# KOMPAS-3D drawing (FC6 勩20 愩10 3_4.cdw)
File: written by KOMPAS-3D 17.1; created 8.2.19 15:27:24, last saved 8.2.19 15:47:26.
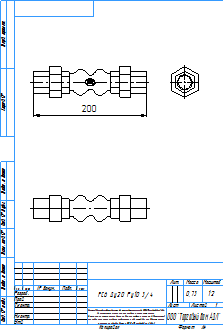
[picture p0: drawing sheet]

Sheet 1: A4, portrait

Title block, sheet 1: name: FC6 Ду20 Ру10 3/4; mass: 0,73; sheets: 1; sheet format: A4; stored path: \\adlc.lan\data\АДЛ_ПКД\3D-модели\ADL production\Гибкие вставки серии FC\FC6\KOMPAS 2D\FC6 Ду20 Ру10 3_4.cdw

Views: Вид 1
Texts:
  kka
  adl
  Рама для чертежей
  Лит-Масса-Масштаб
  Материал-Предприятие
  Масштаб
  Изм.
  Лист
  № докум.
  Подп.
  Дата
  Лит.
  Разраб.
  Пров.
  Т.контр.
  Листов
  Внимание! Данный продукт является объектом авторского права ООО «Торговый Дом АДЛ».
  Запрещается изменение, копирование, распространение
  (в том числе путем копирования на другие сайты и ресурсы в Интернете)
  или любое иное использование информации и объектов без предварительного
  согласия правообладателя (ООО «Торговый Дом АДЛ»).
  Н.контр.
  Утв.
  ООО "Торговый дом АДЛ"
  Изменение
  Номер документа
  Подпись
  Обозначение документа
  Наименование изделия
  Масса изделия по ГОСТ 2.109-73
  Порядковый номер листа
  Общее количество листов в документе
  Характер работы, выполненной лицом, подписавшим документ
  Наименование или индекс предприятия, выпускающего документ
  Инв. № подл.
  Подп. и дата
  Взам. инв. №
  Инв. № дубл.
  Инвентарный номер подлинника по ГОСТ 2.501-68
  Подпись принявшего подлинник в отдел технической документации
  Инвентарный номер подлинника, взамен которого выпущен данный подлинник
  Инвентарный номер дубликата по ГОСТ 2.502-68
  Подпись принявшего дубликат в отдел технической документации
  Справ. №
  Перв. примен.
  Обозначение документа, взамен или на основании которого выпущен данный документ
  Обозначение документа, в котором впервые записан данный документ
  Подпись лица, копировавшего чертеж
  Обозначение формата листа
  !Рама для чертежа
Dimensions and other numbers on the sheet: 200; 1:2; 1; 0,73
